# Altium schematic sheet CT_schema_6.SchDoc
size 366 x 245 mm
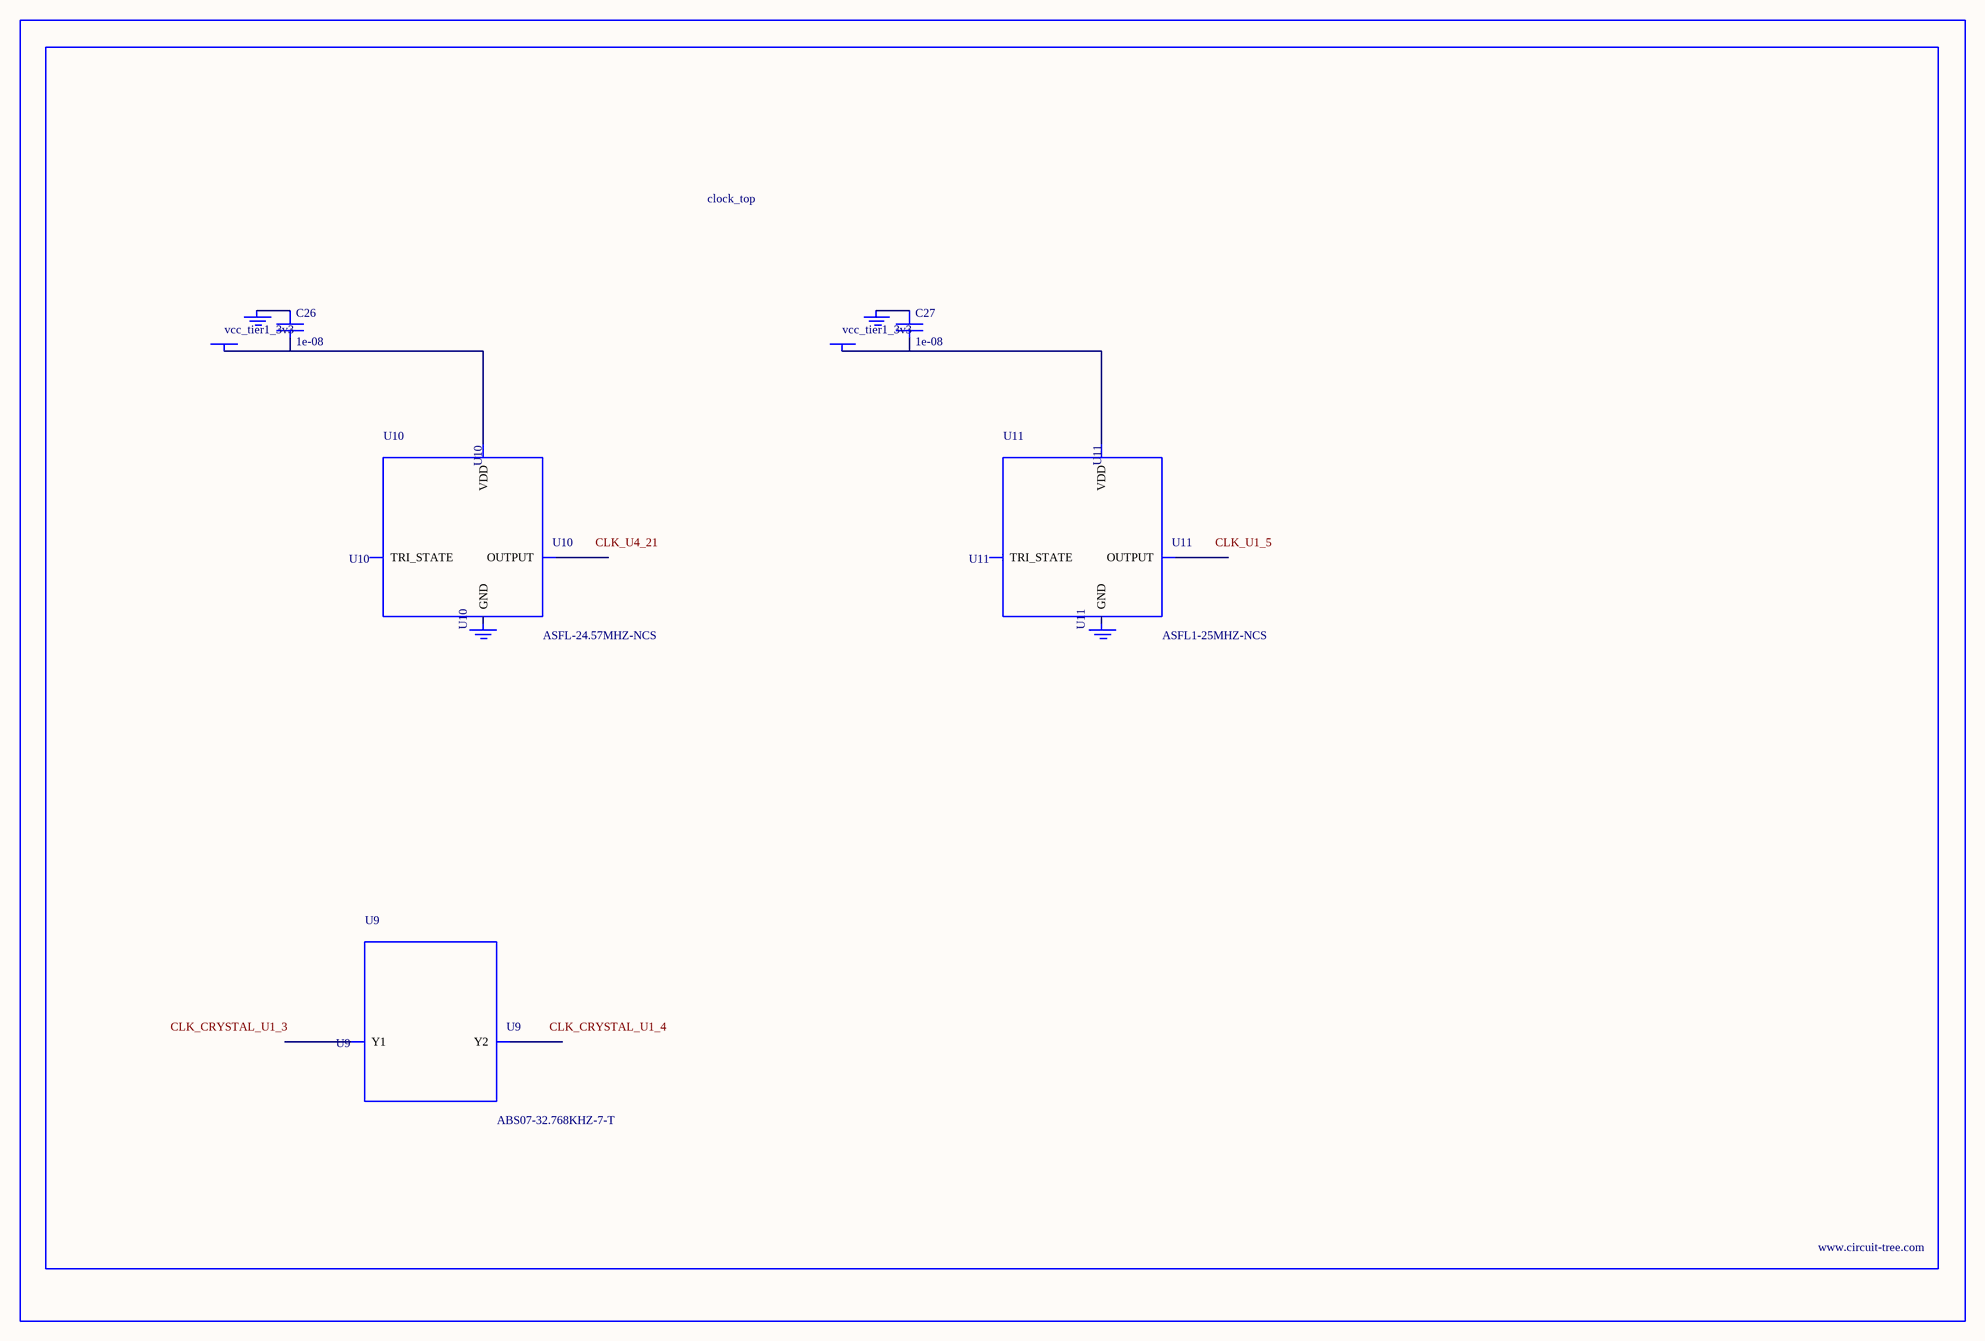
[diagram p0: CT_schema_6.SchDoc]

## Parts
BORDER5  (no value)
C26  1e-08  [C0402]
C27  1e-08  [C0402]
GND_INSTANCE_5_0  (no value)
GND_INSTANCE_5_1  (no value)
GND_INSTANCE_5_2  (no value)
GND_INSTANCE_5_3  (no value)
POWER_INSTANCE_5_0  vcc_tier1_3v3
POWER_INSTANCE_5_1  vcc_tier1_3v3
U9  ABS07-32.768KHZ-7-T  [ABS07-32.768KHZ-7-T]
U10  ASFL-24.57MHZ-NCS  [ASFL1]
U11  ASFL1-25MHZ-NCS  [ASFL1]

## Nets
NetC26_1: C26.1 GND_INSTANCE_5_0.0(GND)
NetC26_2: C26.2 POWER_INSTANCE_5_0.0(PWR) U10.4(VDD)
NetC27_1: C27.1 GND_INSTANCE_5_2.0(GND)
NetC27_2: C27.2 POWER_INSTANCE_5_1.0(PWR) U11.4(VDD)

Not connected (* = marked no-connect by the designer): GND_INSTANCE_5_1 0(GND); GND_INSTANCE_5_3 0(GND); U9 1(Y1) 2(Y2); U10 1(TRI_STATE) 2(GND) 3(OUTPUT); U11 1(TRI_STATE) 2(GND) 3(OUTPUT)

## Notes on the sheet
- Labels drawn without touching a wire or pin: CLK_CRYSTAL_U1_3, CLK_CRYSTAL_U1_4, CLK_U1_5, CLK_U4_21

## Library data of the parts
BORDER5 = BORDER_PAGE5
C26 C27 = C0402C103K3RAC
GND_INSTANCE_5_0-GND_INSTANCE_5_3 = GND
POWER_INSTANCE_5_0 POWER_INSTANCE_5_1 = PWR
